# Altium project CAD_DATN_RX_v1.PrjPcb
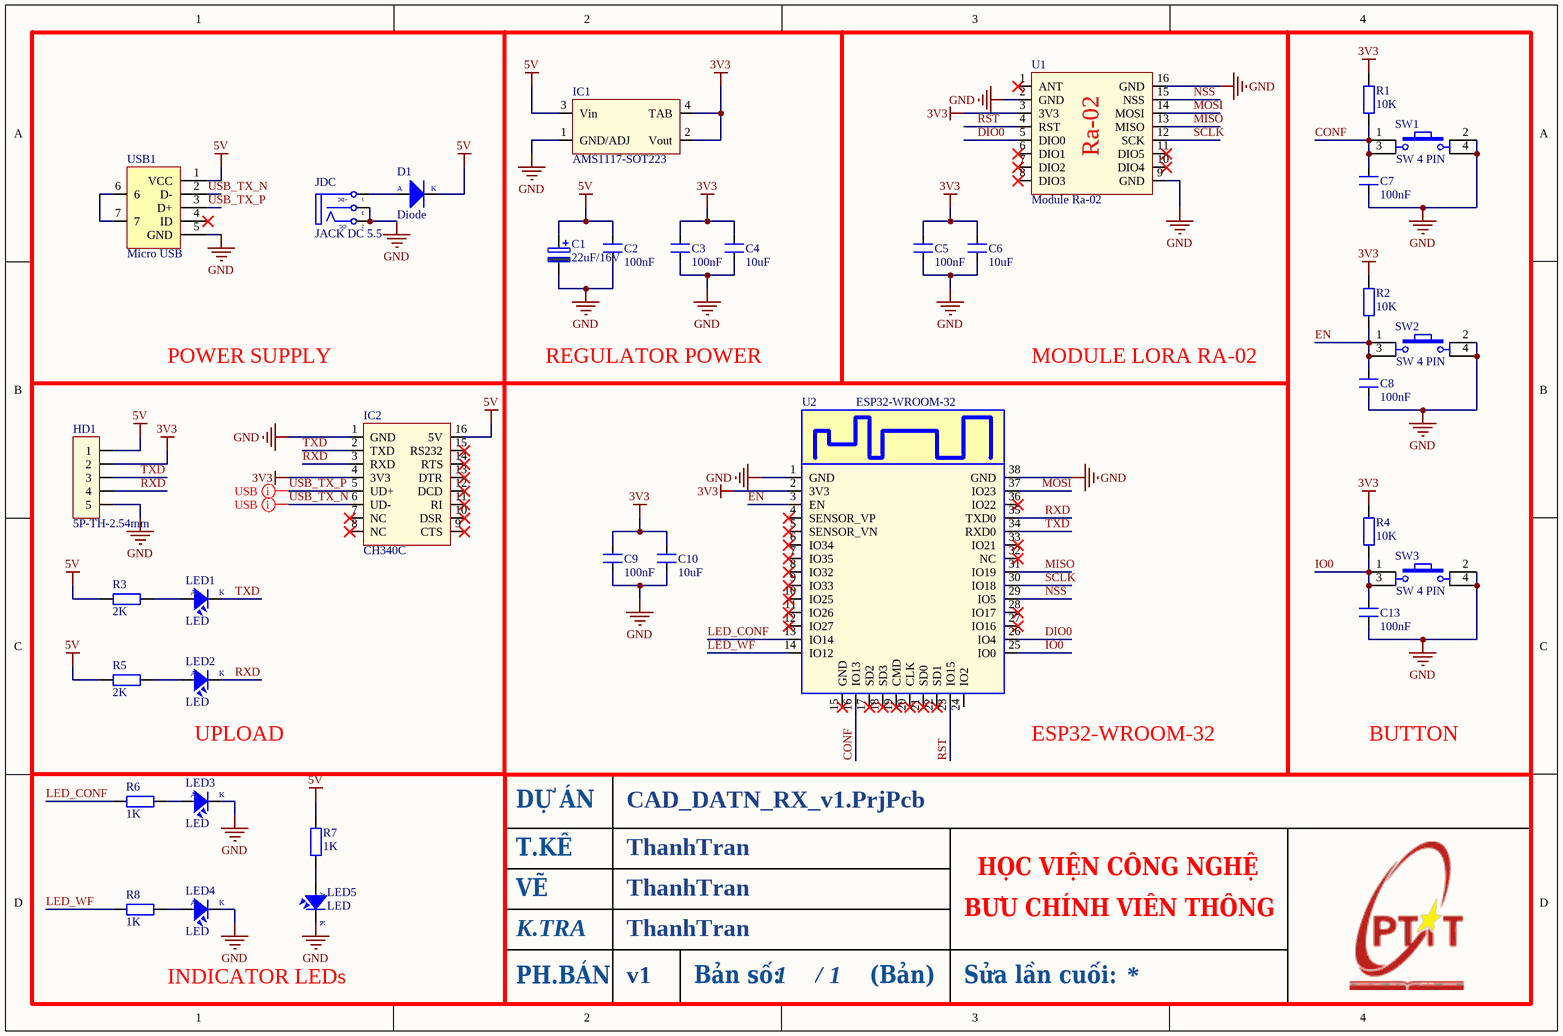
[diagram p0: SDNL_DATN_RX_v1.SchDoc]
1 sheet, 35 parts. Net scope: global (net labels, ports and power ports of the same name join across sheets).
Board file: PCB_DATN_RX_v1.PcbDoc

## Sheet SDNL_DATN_RX_v1.SchDoc
size A4; ApprovedBy: ThanhTran; CheckedBy: ThanhTran; Author: ThanhTran; DrawnBy: ThanhTran; Revision: v1; SheetNumber: 1; SheetTotal: 1

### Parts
C1  22uF/16V  [Cap Aluminum 4x5.4]
C2  100nF  [CAP SMD 0805]
C3  100nF  [CAP SMD 0805]
C4  10uF  [CAP SMD 0805]
C5  100nF  [CAP SMD 0805]
C6  10uF  [CAP SMD 0805]
C7  100nF  [CAP SMD 0805]
C8  100nF  [CAP SMD 0805]
C9  100nF  [CAP SMD 0805]
C10  10uF  [CAP SMD 0805]
C13  100nF  [CAP SMD 0805]
D1  Diode  [DIODE SMA]
HD1  5P-TH-2.54mm  [XH2.54-5P]
IC1  AMS1117-SOT223  [AMS1117-SOT223]
IC2  CH340C  [SOP-16]
JDC  JACK DC 5.5  [DC IN]
LED1  LED  [LED SMD 0805]
LED2  LED  [LED SMD 0805]
LED3  LED  [LED SMD 0805]
LED4  LED  [LED SMD 0805]
LED5  LED  [LED SMD 0805]
R1  10K  [RES SMD 0805]
R2  10K  [RES SMD 0805]
R3  2K  [RES SMD 0805]
R4  10K  [RES SMD 0805]
R5  2K  [RES SMD 0805]
R6  1K  [RES SMD 0805]
R7  1K  [RES SMD 0805]
R8  1K  [RES SMD 0805]
SW1  SW 4 PIN  [SW 4 PIN TH]
SW2  SW 4 PIN  [SW 4 PIN TH]
SW3  SW 4 PIN  [SW 4 PIN TH]
U1  Module Ra-02  [module ra02]
U2  ESP32-WROOM-32  [ESP32-WROOM-32]
USB1  Micro USB  [MICRO USB CONNECTOR]

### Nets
3V3: C3.2 C4.2 C5.2 C6.2 C9.2 C10.2 HD1.2 IC1.2(Vout) IC1.4(TAB) IC2.4(3V3) R1.2 R2.2 R4.2 U1.3(3V3) U2.2(3V3)
5V: C1.1 C2.2 D1.2(K) HD1.1 IC1.3(Vin) IC2.16(5V) R3.2 R5.2 R7.1 USB1.1(VCC)
GND: C1.2 C2.1 C3.1 C4.1 C5.1 C6.1 C7.1 C8.1 C9.1 C10.1 C13.1 HD1.5 IC1.1(GND/ADJ) IC2.1(GND) JDC.2(TN) JDC.3(S) LED3.2(K) LED4.2(K) LED5.2(K) SW1.2 SW1.4 SW2.2 SW2.4 SW3.2 SW3.4 U1.2(GND) U1.9(GND) U1.16(GND) U2.1(GND) U2.38(GND) USB1.5(GND)
CONF: C7.2 R1.1 SW1.1 SW1.3 U2.16(IO13)
DIO0: U1.5(DIO0) U2.26(IO4)
EN: C8.2 R2.1 SW2.1 SW2.3 U2.3(EN)
IO0: C13.2 R4.1 SW3.1 SW3.3 U2.25(IO0)
LED_CONF: R6.1 U2.13(IO14)
LED_WF: R8.1 U2.14(IO12)
MISO: U1.13(MISO) U2.31(IO19)
MOSI: U1.14(MOSI) U2.37(IO23)
NSS: U1.15(NSS) U2.29(IO5)
RST: U1.4(RST) U2.23(IO15)
RXD: HD1.4 IC2.3(RXD) LED2.2(K) U2.35(TXD0)
SCLK: U1.12(SCK) U2.30(IO18)
TXD: HD1.3 IC2.2(TXD) LED1.2(K) U2.34(RXD0)
USB_TX_N: IC2.6(UD-) USB1.2(D-)
USB_TX_P: IC2.5(UD+) USB1.3(D+)
NetD1_1: D1.1(A) JDC.1(T)
NetLED1_1: LED1.1(A) R3.1
NetLED2_1: LED2.1(A) R5.1
NetLED3_1: LED3.1(A) R6.2
NetLED4_1: LED4.1(A) R8.2
NetLED5_1: LED5.1(A) R7.2
NetUSB1_6: USB1.6 USB1.7

Not connected (* = marked no-connect by the designer): IC2 7(NC)* 8(NC)* 9(CTS)* 10(DSR)* 11(RI)* 12(DCD)* 13(DTR)* 14(RTS)* 15(RS232)*; U1 1(ANT)* 6(DIO1)* 7(DIO2)* 8(DIO3)* 10(DIO4)* 11(DIO5)*; U2 4(SENSOR_VP)* 5(SENSOR_VN)* 6(IO34)* 7(IO35)* 8(IO32)* 9(IO33)* 10(IO25)* 11(IO26)* 12(IO27)* 15(GND)* 17(SD2)* 18(SD3)* 19(CMD)* 20(CLK)* 21(SD0)* 22(SD1)* 24(IO2) 27(IO16)* 28(IO17)* 32(NC)* 33(IO21)* 36(IO22)*; USB1 4(ID)*

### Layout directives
differential pair: USB_TX_N, USB_TX_P

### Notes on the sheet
- POWER SUPPLY
- REGULATOR POWER
- MODULE LORA RA-02
- UPLOAD
- (near U2) ESP32-WROOM-32
- BUTTON
- INDICATOR LEDs

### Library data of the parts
C1 = Capacitor Polarity: CAP ALUMINUM
C2 C3 C5 C7-C9 C13 = CM: CM 0805; Value: 103
C4 C6 C10 = CM: Cap SMD; Value: 103
HD1 = Con5
IC1 = AMS1117
JDC = DC IN 5.5
LED1-LED5 = LED: LED Single colour Green and Red; Value: LED 3 ly Single Colour
R1-R5 = RM: Resistor SMD; Value: 1K
R6-R8 = RM: Resistor SMD
U1 = Module Ra02
USB1 = Micro USB Connector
